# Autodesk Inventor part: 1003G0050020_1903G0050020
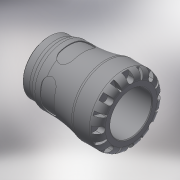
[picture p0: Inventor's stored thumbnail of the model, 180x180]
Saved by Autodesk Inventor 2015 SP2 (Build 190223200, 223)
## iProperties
Created: 2016-12
Part Number: 1003G0050020_1903G0050020
Material: Generic
Description: PLASSON FEMALE ADAPTOR 50x2" SERIES 1
Document SubType Name: Modeling
Designer: KIM
Mass: 292.792 g
Surface Area: 555.371 cm^2
Volume: 292.792 cm^3
Density: 1 g/cm^3
Appearance: Default
Author: KIM
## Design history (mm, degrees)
derived "1003G.ipt"
feature "Solid1::1003G.ipt"
tag "TaggingFeature1"
body "Solid1"
other parameters: "d0" = 118, "d1" = 37.38, "d3" = 62.5, "d4" = 85, "d6" = 89, "d8" = 72.25, "d13" = 9, "d14" = 9, "d15" = 0, "d17" = 360 deg, "d19" = 8 deg, "d20" = 1, "d21" = 1, "d22" = 8 deg, "d24" = 0, "d26" = 360 deg, "d32" = 8.5, "d33" = 8.5, "d39" = 1.69968, "d42" = 56.656, "d43" = 66.3, "d46" = 4.16667, "d47" = 23, "d48" = 53.8232, "d50" = 1.98, "d51" = 0.85, "d54" = 17.5, "d55" = 11, "d57" = 17.64, "d58" = 0, "d68" = 360 deg, "d72" = 1, "d74" = 0, "d76" = 14.875, "E_" = 85, "H_" = 118, "l_" = 89, "G_" = 56.656, "l_2" = 23, "d9" = 11.25, "d11" = 85, "d12" = 62.5, "d49" = 6
